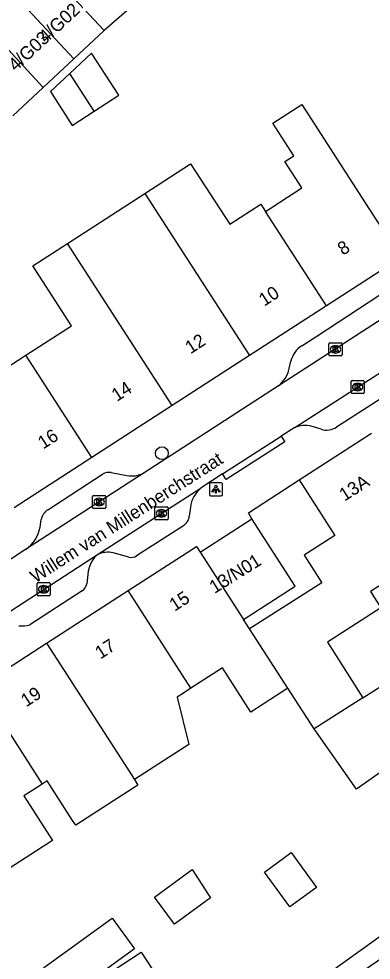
# Model space of a CAD drawing. Extents: x 161801 to 162379, y 382315 to 382832.
# Drawn here: x 161942.5 to 161969.4, y 382565.6 to 382637.3 of the extents above; entities that cross this region are included whole.
import ezdxf

# ---------------------------------------------------------------- set-up
doc = ezdxf.new("R2010")
doc.units = 0
for name, color, linetype in [('IMGEO_Boom', 7, 'Continuous'), ('IMGEO_Kolk', 7, 'Continuous'), ('IMGEO_Lichtpunt', 7, 'Continuous'), ('IMGEO_Openbare_ruimte_label', 7, 'Continuous'), ('IMGEO_Pand', 7, 'Continuous'), ('IMGEO_Pand_nummerreeks', 7, 'Continuous'), ('IMGEO_Rijbaan_lokaal_open', 7, 'Continuous'), ('IMGEO_Voetpad_open', 7, 'Continuous')]:
    doc.layers.add(name, color=color, linetype=linetype)

msp = doc.modelspace()

# ---------------------------------------------------------------- linework, layer by layer
at = {"layer": 'IMGEO_Boom'}
msp.add_circle((161953.401, 382604.225), 0.489, dxfattribs=at)
at = {"layer": 'IMGEO_Kolk'}
for p, q in [((161966.134, 382611.71), (161966.134, 382612.562)), ((161966.209, 382612.636), (161967.061, 382612.636)), ((161967.135, 382612.562), (161967.135, 382611.71)), ((161966.645, 382611.856), (161966.62, 382611.856)), ((161966.622, 382612.416), (161966.647, 382612.416)), ((161967.061, 382611.636), (161966.209, 382611.636)), ((161967.819, 382608.84), (161967.819, 382609.692)), ((161967.894, 382609.766), (161968.746, 382609.766)), ((161968.82, 382609.692), (161968.82, 382608.84)), ((161968.33, 382608.986), (161968.305, 382608.986)), ((161968.307, 382609.546), (161968.332, 382609.546)), ((161968.746, 382608.766), (161967.894, 382608.766)), ((161948.191, 382601.011), (161949.043, 382601.011)), ((161948.116, 382600.085), (161948.116, 382600.937)), ((161948.627, 382600.231), (161948.602, 382600.231)), ((161948.604, 382600.791), (161948.629, 382600.791)), ((161949.117, 382600.937), (161949.117, 382600.085)), ((161949.043, 382600.011), (161948.191, 382600.011)), ((161952.866, 382599.221), (161952.866, 382600.073)), ((161952.941, 382600.147), (161953.793, 382600.147)), ((161953.354, 382599.927), (161953.379, 382599.927)), ((161953.867, 382600.073), (161953.867, 382599.221)), ((161953.793, 382599.147), (161952.941, 382599.147)), ((161953.377, 382599.367), (161953.352, 382599.367)), ((161943.893, 382593.438), (161943.893, 382594.29)), ((161943.968, 382594.364), (161944.82, 382594.364)), ((161944.381, 382594.144), (161944.406, 382594.144)), ((161944.894, 382594.29), (161944.894, 382593.438)), ((161944.82, 382593.364), (161943.968, 382593.364)), ((161944.404, 382593.584), (161944.379, 382593.584))]:
    msp.add_line(p, q, dxfattribs=at)
for points in [[(161966.134, 382611.71), (161966.134, 382612.562)], [(161966.209, 382612.636), (161967.061, 382612.636)], [(161967.135, 382612.562), (161967.135, 382611.71)], [(161966.455, 382612.336), (161966.578, 382612.336), (161966.578, 382612.185), (161966.708, 382612.336), (161966.872, 382612.336), (161966.726, 382612.185), (161966.879, 382611.936), (161966.727, 382611.936), (161966.642, 382612.1), (161966.578, 382612.033), (161966.578, 382611.936), (161966.455, 382611.936), (161966.455, 382612.336)], [(161967.061, 382611.636), (161966.209, 382611.636)], [(161967.819, 382608.84), (161967.819, 382609.692)], [(161967.894, 382609.766), (161968.746, 382609.766)], [(161968.82, 382609.692), (161968.82, 382608.84)], [(161968.14, 382609.466), (161968.263, 382609.466), (161968.263, 382609.315), (161968.393, 382609.466), (161968.557, 382609.466), (161968.411, 382609.315), (161968.564, 382609.066), (161968.412, 382609.066), (161968.327, 382609.23), (161968.263, 382609.163), (161968.263, 382609.066), (161968.14, 382609.066), (161968.14, 382609.466)], [(161968.746, 382608.766), (161967.894, 382608.766)], [(161948.191, 382601.011), (161949.043, 382601.011)], [(161948.116, 382600.085), (161948.116, 382600.937)], [(161948.437, 382600.711), (161948.56, 382600.711), (161948.56, 382600.56), (161948.69, 382600.711), (161948.854, 382600.711), (161948.708, 382600.56), (161948.861, 382600.311), (161948.709, 382600.311), (161948.624, 382600.475), (161948.56, 382600.408), (161948.56, 382600.311), (161948.437, 382600.311), (161948.437, 382600.711)], [(161949.117, 382600.937), (161949.117, 382600.085)], [(161949.043, 382600.011), (161948.191, 382600.011)], [(161952.866, 382599.221), (161952.866, 382600.073)], [(161952.941, 382600.147), (161953.793, 382600.147)], [(161953.187, 382599.847), (161953.31, 382599.847), (161953.31, 382599.696), (161953.44, 382599.847), (161953.604, 382599.847), (161953.458, 382599.696), (161953.611, 382599.447), (161953.459, 382599.447), (161953.374, 382599.611), (161953.31, 382599.544), (161953.31, 382599.447), (161953.187, 382599.447), (161953.187, 382599.847)], [(161953.867, 382600.073), (161953.867, 382599.221)], [(161953.793, 382599.147), (161952.941, 382599.147)], [(161943.893, 382593.438), (161943.893, 382594.29)], [(161943.968, 382594.364), (161944.82, 382594.364)], [(161944.214, 382594.064), (161944.337, 382594.064), (161944.337, 382593.913), (161944.467, 382594.064), (161944.631, 382594.064), (161944.485, 382593.913), (161944.638, 382593.664), (161944.486, 382593.664), (161944.401, 382593.828), (161944.337, 382593.761), (161944.337, 382593.664), (161944.214, 382593.664), (161944.214, 382594.064)], [(161944.894, 382594.29), (161944.894, 382593.438)], [(161944.82, 382593.364), (161943.968, 382593.364)]]:
    msp.add_lwpolyline(points, dxfattribs=at)
for centre, start, end in [((161966.211, 382612.56), 91.55205, 178.44795), ((161966.211, 382612.56), 91.55205, 178.44795), ((161967.059, 382612.56), 1.55205, 88.44795), ((161967.059, 382612.56), 1.55205, 88.44795), ((161966.211, 382611.712), 181.55205, 268.44795), ((161966.211, 382611.712), 181.55205, 268.44795), ((161967.059, 382611.712), 271.55205, 358.44795), ((161967.059, 382611.712), 271.55205, 358.44795), ((161967.896, 382609.69), 91.55205, 178.44795), ((161967.896, 382609.69), 91.55205, 178.44795), ((161968.744, 382609.69), 1.55205, 88.44795), ((161968.744, 382609.69), 1.55205, 88.44795), ((161967.896, 382608.842), 181.55205, 268.44795), ((161967.896, 382608.842), 181.55205, 268.44795), ((161968.744, 382608.842), 271.55205, 358.44795), ((161968.744, 382608.842), 271.55205, 358.44795), ((161948.193, 382600.935), 91.55205, 178.44795), ((161948.193, 382600.935), 91.55205, 178.44795), ((161949.041, 382600.935), 1.55205, 88.44795), ((161949.041, 382600.935), 1.55205, 88.44795), ((161948.193, 382600.087), 181.55205, 268.44795), ((161948.193, 382600.087), 181.55205, 268.44795), ((161949.041, 382600.087), 271.55205, 358.44795), ((161949.041, 382600.087), 271.55205, 358.44795), ((161952.943, 382600.071), 91.55205, 178.44795), ((161952.943, 382600.071), 91.55205, 178.44795), ((161953.791, 382600.071), 1.55205, 88.44795), ((161953.791, 382600.071), 1.55205, 88.44795), ((161952.943, 382599.223), 181.55205, 268.44795), ((161952.943, 382599.223), 181.55205, 268.44795), ((161953.791, 382599.223), 271.55205, 358.44795), ((161953.791, 382599.223), 271.55205, 358.44795), ((161943.97, 382594.288), 91.55205, 178.44795), ((161943.97, 382594.288), 91.55205, 178.44795), ((161944.818, 382594.288), 1.55205, 88.44795), ((161944.818, 382594.288), 1.55205, 88.44795), ((161943.97, 382593.44), 181.55205, 268.44795), ((161943.97, 382593.44), 181.55205, 268.44795), ((161944.818, 382593.44), 271.55205, 358.44795), ((161944.818, 382593.44), 271.55205, 358.44795)]:
    msp.add_arc(centre, 0.0765, start, end, dxfattribs=at)
for centre, major_axis, ratio, start_param, end_param in [((161966.621, 382612.136), (-0.387, 0.002), 0.722429, 4.712389, 7.853982), ((161966.646, 382612.136), (-0.39, 0.002), 0.717154, 1.570796, 4.712389), ((161968.306, 382609.266), (-0.387, 0.002), 0.722429, 4.712389, 7.853982), ((161968.331, 382609.266), (-0.39, 0.002), 0.717154, 1.570796, 4.712389), ((161948.603, 382600.511), (-0.387, 0.002), 0.722429, 4.712389, 7.853982), ((161948.628, 382600.511), (-0.39, 0.002), 0.717154, 1.570796, 4.712389), ((161953.353, 382599.647), (-0.387, 0.002), 0.722429, 4.712389, 7.853982), ((161953.378, 382599.647), (-0.39, 0.002), 0.717154, 1.570796, 4.712389), ((161944.38, 382593.864), (-0.387, 0.002), 0.722429, 4.712389, 7.853982), ((161944.405, 382593.864), (-0.39, 0.002), 0.717154, 1.570796, 4.712389)]:
    msp.add_ellipse(centre, major_axis=major_axis, ratio=ratio, start_param=start_param, end_param=end_param, dxfattribs=at)
at = {"layer": 'IMGEO_Lichtpunt'}
for p, q in [((161957.023, 382601.883), (161957.023, 382601.076)), ((161957.023, 382601.883), (161957.023, 382601.076)), ((161957.925, 382601.978), (161957.117, 382601.978)), ((161957.925, 382601.978), (161957.117, 382601.978)), ((161958.019, 382601.076), (161958.019, 382601.883)), ((161958.019, 382601.076), (161958.019, 382601.883)), ((161957.117, 382600.982), (161957.925, 382600.982)), ((161957.117, 382600.982), (161957.925, 382600.982))]:
    msp.add_line(p, q, dxfattribs=at)
for points in [[(161957.397, 382601.547), (161957.436, 382601.519), (161957.248, 382601.257), (161957.21, 382601.284), (161957.397, 382601.547)], [(161957.499, 382601.499), (161957.546, 382601.499), (161957.546, 382601.177), (161957.499, 382601.177), (161957.499, 382601.499)], [(161957.609, 382601.519), (161957.647, 382601.546), (161957.834, 382601.284), (161957.795, 382601.256), (161957.609, 382601.519)]]:
    msp.add_lwpolyline(points, dxfattribs=at)
msp.add_circle((161957.522, 382601.681), 0.0994, dxfattribs=at)
for centre, start, end in [((161957.117, 382601.883), 90, 180), ((161957.117, 382601.883), 90, 180), ((161957.925, 382601.883), 0, 90), ((161957.925, 382601.883), 0, 90), ((161957.117, 382601.076), 180, 270), ((161957.117, 382601.076), 180, 270), ((161957.925, 382601.076), 270, 0), ((161957.925, 382601.076), 270, 360)]:
    msp.add_arc(centre, 0.0946, start, end, dxfattribs=at)
at = {"layer": 'IMGEO_Pand'}
for points in [[(161949.005, 382636.425), (161945.163, 382640.546)], [(161946.681, 382634.263), (161942.842, 382638.382)], [(161951.321, 382638.442), (161949.005, 382636.425)], [(161940.52, 382636.218), (161944.36, 382632.099)], [(161949.005, 382636.425), (161946.681, 382634.263)], [(161948.244, 382630.273), (161950.113, 382631.498), (161948.041, 382634.703), (161946.381, 382633.155)], [(161946.681, 382634.263), (161944.36, 382632.099)], [(161946.381, 382633.155), (161944.9, 382631.775), (161946.576, 382629.181), (161948.244, 382630.273)], [(161948.244, 382630.273), (161946.381, 382633.155)], [(161944.36, 382632.099), (161942.038, 382629.935)], [(161961.304, 382622.652), (161961.567, 382622.822), (161962.388, 382623.353), (161964.077, 382624.445), (161962.78, 382626.452), (161963.46, 382626.891), (161961.862, 382629.364), (161964.056, 382630.783), (161968.889, 382623.305), (161971.603, 382619.106)], [(161952.091, 382624.018), (161955.594, 382626.282), (161958.578, 382621.665), (161960.951, 382623.198), (161961.304, 382622.652)], [(161946.198, 382620.211), (161952.091, 382624.018)], [(161952.091, 382624.018), (161960.078, 382611.658)], [(161965.954, 382615.456), (161961.304, 382622.652)], [(161943.037, 382611.685), (161946.515, 382613.933), (161943.56, 382618.506), (161946.198, 382620.211)], [(161954.188, 382607.852), (161946.198, 382620.211)], [(161971.603, 382619.106), (161965.954, 382615.456)], [(161965.954, 382615.456), (161960.078, 382611.658)], [(161934.272, 382612.252), (161934.142, 382612.454), (161937.273, 382614.477), (161940.244, 382609.881), (161943.037, 382611.685)], [(161948.069, 382603.898), (161943.037, 382611.685)], [(161960.078, 382611.658), (161954.188, 382607.852)], [(161954.188, 382607.852), (161948.069, 382603.898)], [(161963.857, 382602.208), (161969.381, 382605.744)], [(161948.069, 382603.898), (161942.145, 382600.07)], [(161963.857, 382602.208), (161966.576, 382597.953), (161964.242, 382596.461), (161965.588, 382594.354), (161960.087, 382590.84)], [(161956.316, 382596.694), (161960.267, 382599.238)], [(161959.62, 382591.565), (161963.571, 382594.109), (161960.267, 382599.238)], [(161950.82, 382593.758), (161956.041, 382597.121), (161956.316, 382596.694)], [(161956.316, 382596.694), (161959.62, 382591.565)], [(161974.848, 382597.222), (161969.306, 382593.681), (161970.097, 382592.442), (161966.011, 382589.831), (161968.719, 382585.592)], [(161944.614, 382589.761), (161950.82, 382593.758)], [(161955.611, 382586.318), (161950.82, 382593.758)], [(161960.087, 382590.84), (161959.62, 382591.565)], [(161962.999, 382586.319), (161960.087, 382590.84)], [(161968.719, 382585.592), (161972.494, 382588.005), (161973.129, 382587.1), (161977.878, 382590.828), (161979.727, 382588.474)], [(161939.49, 382586.461), (161944.614, 382589.761)], [(161944.614, 382589.761), (161951.307, 382579.365)], [(161962.999, 382586.319), (161960.178, 382584.502), (161958.012, 382587.864), (161955.611, 382586.318)], [(161939.49, 382586.461), (161944.28, 382579.022)], [(161955.611, 382586.318), (161955.132, 382586.009), (161954.563, 382585.643), (161955.46, 382582.039), (161951.307, 382579.365)], [(161965.016, 382583.226), (161962.999, 382586.319)], [(161968.719, 382585.592), (161965.016, 382583.226)], [(161973.21, 382583.357), (161972.736, 382582.985), (161972.163, 382581.401), (161968.23, 382578.643), (161965.016, 382583.226)], [(161944.28, 382579.022), (161943.569, 382578.564), (161942.874, 382578.117), (161945.057, 382574.729), (161940.162, 382571.576)], [(161951.307, 382579.365), (161951.575, 382578.949), (161948.927, 382577.243), (161946.831, 382575.893), (161946.596, 382576.256), (161944.658, 382579.265), (161944.28, 382579.022)], [(161961.215, 382572.31), (161963.252, 382573.799), (161965.189, 382571.15), (161963.151, 382569.661), (161961.215, 382572.31)], [(161954.353, 382568.337), (161952.84, 382570.406), (161955.72, 382572.51), (161956.964, 382570.579), (161957.11, 382570.352), (161954.353, 382568.337)], [(161944.377, 382565.031), (161949.608, 382568.813), (161951.303, 382566.468), (161945.946, 382562.594)], [(161951.179, 382557.869), (161947.547, 382563.429), (161951.82, 382566.221), (161955.452, 382560.66), (161951.179, 382557.869)]]:
    msp.add_lwpolyline(points, dxfattribs=at)
at = {"layer": 'IMGEO_Rijbaan_lokaal_open'}
for points in [[(161963.527, 382606.175), (161991.516, 382624.16)], [(161979.975, 382620.785), (161962.299, 382609.357)], [(161962.299, 382609.357), (161954.989, 382604.626), (161952.043, 382602.73)], [(161963.527, 382606.175), (161962.494, 382605.525)], [(161958.032, 382602.652), (161962.494, 382605.525)], [(161952.043, 382602.73), (161943.005, 382596.884)], [(161958.032, 382602.652), (161956.401, 382601.588)], [(161948.497, 382596.51), (161956.401, 382601.588)], [(161943.005, 382596.884), (161941.966, 382596.213), (161934.803, 382591.618)], [(161940.347, 382591.237), (161948.497, 382596.51)]]:
    msp.add_lwpolyline(points, dxfattribs=at)
at = {"layer": 'IMGEO_Voetpad_open'}
for points in [[(161990.151, 382621.263), (161979.093, 382614.157), (161966.706, 382606.212)], [(161964.054, 382612.406), (161965.198, 382613.143), (161973.999, 382618.904), (161977.056, 382620.852)], [(161963.106, 382610.675), (161963.23, 382611.226)], [(161965.55, 382606.049), (161964.789, 382606.276)], [(161962.494, 382605.525), (161962.764, 382605.105), (161958.302, 382602.232), (161958.032, 382602.652)], [(161944.701, 382599.92), (161948.879, 382602.619)], [(161949.533, 382602.748), (161950.726, 382602.525)], [(161960.267, 382599.238), (161960.005, 382599.676), (161963.857, 382602.208)], [(161955.574, 382600.107), (161955.49, 382599.423)], [(161944.116, 382598.581), (161944.212, 382599.173)], [(161955.039, 382598.703), (161951.476, 382596.409)], [(161950.881, 382596.314), (161949.677, 382596.629)], [(161947.794, 382595.246), (161947.674, 382594.278)], [(161947.336, 382593.74), (161943.339, 382591.163)], [(161991.153, 382551.961), (161991.121, 382552.009), (161992.14, 382552.651), (161987.811, 382559.519), (161983.621, 382566.165), (161979.755, 382572.298), (161967.811, 382564.144), (161978.347, 382548.711), (161976.906, 382547.794), (161967.106, 382563.196), (161966.173, 382564.661), (161979.378, 382574.126)]]:
    msp.add_lwpolyline(points, dxfattribs=at)
for centre, radius, start, end in [((161965.084, 382610.809), 1.901, 122.82739, 167.31903), ((161960.76, 382611.205), 2.405, 309.77953, 347.26292), ((161964.289, 382604.589), 1.759, 73.48462, 115.66683), ((161965.951, 382607.387), 1.397, 253.33173, 302.72026), ((161949.366, 382601.875), 0.889, 79.1488, 123.16764), ((161951.096, 382604.481), 1.991, 259.29278, 298.40218), ((161957.798, 382599.837), 2.24, 128.57202, 173.06943), ((161945.292, 382599), 1.094, 122.69659, 170.88441), ((161954.498, 382599.543), 0.999, 302.78605, 353.08881), ((161941.549, 382599.05), 2.61, 303.92116, 349.65453), ((161949.253, 382594.922), 1.759, 76.05388, 115.46345), ((161949.855, 382594.927), 2.085, 130.62503, 171.2119), ((161951.07, 382597.039), 0.749, 255.37017, 302.77282), ((161946.786, 382594.461), 0.907, 307.35925, 348.36234), ((161942.654, 382593.455), 2.392, 266.2365, 286.63803)]:
    msp.add_arc(centre, radius, start, end, dxfattribs=at)

# ---------------------------------------------------------------- texts
at = {"layer": 'IMGEO_Openbare_ruimte_label'}
msp.add_text('Willem van Millenberchstraat', height=1, rotation=32.67328, dxfattribs=at).set_placement((161943.766, 382594.298))
at = {"layer": 'IMGEO_Pand_nummerreeks'}
for s, rotation, p in [('4/G02', 42.90475, (161944.566, 382635.402)), ('4/G03', 42.90475, (161942.26, 382633.259)), ('8', 32.87059, (161967.2, 382619.262)), ('10', 32.87059, (161961.2, 382615.384)), ('12', 32.87095, (161955.581, 382611.753)), ('14', 32.87095, (161949.971, 382608.127)), ('16', 32.87059, (161944.357, 382604.5)), ('13A', 32.616, (161967.32, 382600.53)), ('13/N01', 31.94997, (161957.414, 382593.497)), ('15', 32.78553, (161954.372, 382592.144)), ('17', 32.78465, (161948.717, 382588.502)), ('19', 32.78465, (161943.062, 382584.859))]:
    msp.add_text(s, height=1, rotation=rotation, dxfattribs=at).set_placement(p)

doc.saveas('drawing.dxf')
